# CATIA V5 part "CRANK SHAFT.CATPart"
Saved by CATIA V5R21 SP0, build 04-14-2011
Part number: Part1.1.2
Material "DS Light Blue": density 7860 kg/m3, Young's modulus 2e+11 Pa, Poisson ratio 0.266
Material "DS Light Blue": density 7860 kg/m3, Young's modulus 2e+11 Pa, Poisson ratio 0.266
Material "DS Light Blue": density 7860 kg/m3, Young's modulus 2e+11 Pa, Poisson ratio 0.266
Material "DS Light Blue": density 7860 kg/m3, Young's modulus 2e+11 Pa, Poisson ratio 0.266
Bounding box of the stored display mesh (mm): x -395 to 95, y -59.998 to 59.998, z -92.5 to 92.5
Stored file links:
  G:\CATIA\PROJECT__01\CRANK SHAFT.CATPart
  C:\Program Files (x86)\Dassault Systemes\B21\intel_a\startup\materials\blue_env_512x512.jpg
  C:\Program Files (x86)\Dassault Systemes\B21\intel_a\startup\materials\Catalog.CATMaterial
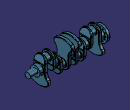
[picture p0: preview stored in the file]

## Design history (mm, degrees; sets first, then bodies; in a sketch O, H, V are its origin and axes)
Body1 "Body 1" (main body), material "DS Light Blue"
  Sketch1 on yz-plane, origin (0, 0, 0), H (0, 1, 0), V (0, 0, 1)
    arc A1 centre (0, 0) radius 92.5 from (-51.0345, -77.1475) to (51.0345, -77.1475) ccw
    arc A2 centre (0, 42) radius 37.5 from (37.5, 42) to (-37.5, 42) ccw
    point P1 (0, 42)
    arc A3 centre (-40, -60.4669) radius 20 from (-53.5714, -45.7762) to (-51.0345, -77.1475) ccw
    line L1 (-37.5, 42) -> (-37.5, -9.0495)
    arc A4 centre (-87.5, -9.0495) radius 50 from (-53.5714, -45.7762) to (-37.5, -9.0495) ccw
    point P4 (-37.5, -9.0495)
    point P5 (-37.5, 42)
    point P6 (-51.0345, -77.1475)
    point P7 (-53.5714, -45.7762)
    reference intersected line E1 through (0, 0) direction (0, 1) from zx-plane
    point P10 (51.0345, -77.1475)
    point P11 (53.5714, -45.7762)
    arc A5 centre (40, -60.4669) radius 20 from (53.5714, -45.7762) to (51.0345, -77.1475) cw
    point P13 (37.5, -9.0495)
    arc A6 centre (87.5, -9.0495) radius 50 from (53.5714, -45.7762) to (37.5, -9.0495) cw
    point P15 (37.5, 42)
    line L2 (37.5, 42) -> (37.5, -9.0495)
    radius A1 = 92.5
    distance P1 O = 42
    radius A2 = 37.5
    radius A3 = 20
    distance O A3 H = 60
    radius A4 = 50
    coincidence: P1 V
    tangency: A3 A1, L1 A2, L1 A4, A4 A3
    vertical: L1 V
    symmetry: P6 P10 E1, P7 P11 E1, A3 A5 E1, P4 P13 E1, A4 A6 E1, P5 P15 E1, L1 L2 E1
  Pad1: profile Sketch1, direction (1, 0, 0), length 20
  Sketch2 on start face of Pad1, origin (0, 0, 0), H (0, -1, 0), V (0, 0, 1)
    circle A1 centre (0, 42) radius 24
    reference projected arc E1 centre (0, 42) radius 37.5 from (37.5, 42) to (-37.5, 42) ccw from edge [start face of Pad1 | face of Pad1 from Sketch1.A2]
    radius A1 = 24
    concentricity: A1 E1
  Pad2: profile Sketch2, direction (-1, 0, 0), length 35
  Sketch3 on end face of Pad2, origin (-35, 0, 0), H (0, -1, 0), V (0, 0, 1)
    projected line E1 (37.5, 42) -> (37.5, -9.0495) from edge [start face of Pad1 | face of Pad1 from Sketch1.L1]
    projected line E2 (37.5, 42) -> (37.5, 0) from edge [start face of Pad1 | face of Pad1 from Sketch1.L1]
    point P1 (37.5, 42)
    projected arc E3 centre (0, 42) radius 37.5 from (37.5, 42) to (-37.5, 42) ccw from edge [start face of Pad1 | face of Pad1 from Sketch1.A2]
    point P3 (37.5, 42)
    point P4 (-37.5, 42)
    projected line E4 (-37.5, -9.0495) -> (-37.5, 42) from edge [start face of Pad1 | face of Pad1 from Sketch1.L2]
    projected line E5 (-37.5, 0) -> (-37.5, 42) from edge [start face of Pad1 | face of Pad1 from Sketch1.L2]
    point P6 (-37.5, 42)
    arc A1 centre (0, 0) radius 37.5 from (-37.5, 0) to (37.5, 0) ccw
    point P7 (-37.5, 0)
    point P8 (37.5, 0)
    tangency: A1 E1
    coincidence: E1 P8, E4 P7, P1 P3, P4 P6
  Pad3: profile Sketch3, direction (-1, 0, 0), length 20
  Sketch4 on end face of Pad1, origin (20, 0, 0), H (0, 1, 0), V (0, 0, 1)
    circle A1 centre (0, 0) radius 31
    radius A1 = 31
  Pad4: profile Sketch4, direction (1, 0, 0), length 25
  Plane1: type Offset, RefPlane start face of Pad1, Offset 17.5, reversed
  Mirror1: of Pad4, about Plane1
  Sketch5 on zx-plane, origin (0, 0, 0), H (-1, 0, 0), V (0, 0, 1)
    reference projected line E1 (35, 0) -> (35, -37.5) from edge [start face of Pad3 | face of Pad3 from Sketch3.A1]
    reference projected line E2 (-20, 42) -> (-20, 79.5) from edge [face of Pad1 from Sketch1.A2 | end face of Pad1]
    point P3 (-20, 42)
    point P4 (-20, 79.5)
    line L1 (35, -37.5) -> (45, -37.5)
    line L2 (45, -37.5) -> (35, 7.5)
    point P6 (35, 7.5)
    line L3 (35, 7.5) -> (35, -37.5)
    line L4 (-20, 79.5) -> (-10, 79.5)
    point P7 (-10, 79.5)
    line L5 (-10, 79.5) -> (-20, 34.5)
    point P8 (-20, 34.5)
    line L6 (-20, 34.5) -> (-20, 79.5)
    reference intersected line E3 through (17.5, 0) direction (0, -1) from Plane1
    point P11 (55, 79.5)
    point P12 (55, 42)
    point P13 (45, 79.5)
    point P14 (55, 34.5)
    line L7 (55, 79.5) -> (45, 79.5)
    line L8 (45, 79.5) -> (55, 34.5)
    line L9 (55, 34.5) -> (55, 79.5)
    construction line L10 (55, 42) -> (55, 79.5)
    length L1 = 10
    length L3 = 45
    length L4 = 10
    length L6 = 45
    horizontal: L1 H, L4 H
    coincidence: P6 E1, P8 E2
    vertical: L3 V, L6 V
    symmetry: P4 P11 E3, P3 P12 E3, E2 L10 E3, P7 P13 E3, P8 P14 E3, L4 L7 E3, L5 L8 E3, L6 L9 E3
  Pocket1: profile Sketch5, direction (0, -1, 0), through (limit type 3), opposite side through (limit type 3)
  Fillet1: radius 25, on edge [face of Pocket1 from Sketch5.L5 | end face of Pad1]; edge [start face of Pad3 | face of Pocket1 from Sketch5.L2]; edge [end face of Pad3 | face of Pocket1 from Sketch5.L8]
  Fillet2: radius 2.5, on edge [face of Pad3 from Sketch3.E3 | face of Pocket1 from Sketch5.L8]; edge [start face of Pad3 | face of Pad3 from Sketch3.E3]; edge [start face of Pad1 | face of Pad1 from Sketch1.A2]; edge [face of Pocket1 from Sketch5.L5 | face of Pad1 from Sketch1.A2]; start face of Pad1; face of Pad2 from Sketch2.A1; edge [end face of Pad1 | face of Pad4 from Sketch4.A1]; end face of Pad3
Body2 "Body 2", material "DS Light Blue"
  Solid1: linked copy from another document
  Plane2: type Offset, RefPlane face of Solid1, Offset 12.5
  Symmetry1: Reference Plane2, ToTransfor Solid1
  Rotate1: Axis X axis, Angle 180, ToTransfor Symmetry1
Body3 "Body 3", material "DS Light Blue"
  Solid2: linked copy from another document
  Plane3: type Offset, RefPlane face of Solid2, Offset 12.5
  Symmetry2: Reference Plane3, ToTransfor Solid2
  Rotate2: Axis X axis, Angle 180, ToTransfor Symmetry2
  Plane4: type Offset, RefPlane face of Solid2, Offset 12.5
  Symmetry3: Reference Plane4, ToTransfor Rotate2
Body4 "Body 4", material "DS Light Blue"
  Solid3: linked copy from another document
  Plane5: type Offset, RefPlane face of Solid3, Offset 12.5
  Symmetry4: Reference Plane5, ToTransfor Solid3
  Rotate3: Axis X axis, Angle 180, ToTransfor Symmetry4
  Plane6: type Offset, RefPlane face of Solid3, Offset 12.5
  Symmetry5: Reference Plane6, ToTransfor Rotate3
  Plane7: type Offset, RefPlane face of Solid3, Offset 12.5
  Symmetry6: Reference Plane7, ToTransfor Symmetry5
  Rotate4: Axis X axis, Angle 180, ToTransfor Symmetry6
  Sketch6 on face of Solid3, origin (-380, 0, 0), H (0, -1, 0), V (0, 0, 1)
    circle A1 centre (0, 0) radius 50
    radius A1 = 50
  Pad5: profile Sketch6, direction (-1, 0, 0), length 15
  Sketch7 on end face of Pad5, origin (-395, 0, 0), H (0, -1, 0), V (0, 0, 1)
    circle A1 centre (0, 37.5) radius 3.75
    point P1 (0, 37.5)
    radius A1 = 3.75
    distance P1 H = 37.5
    coincidence: P1 V
  Pocket2: profile Sketch7, direction (1, 0, 0), through (limit type 6)
  CircPattern1: of Pocket2, instances 12, angular step 30 {= 360.0*1 deg/CircPattern1.AngularNumber}, axis from end face of Pad5
  Sketch8 on end face of Pad4, origin (45, 0, 0), H (0, 1, 0), V (0, 0, 1)
    circle A1 centre (0, 0) radius 17.5
    radius A1 = 17.5
  Pad6: profile Sketch8, direction (1, 0, 0), length 50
